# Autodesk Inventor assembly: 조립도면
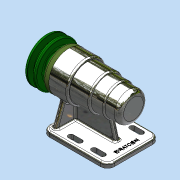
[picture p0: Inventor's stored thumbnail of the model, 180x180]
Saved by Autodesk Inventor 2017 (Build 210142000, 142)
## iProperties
Part Number: 조립도면
Material: 일반
Document SubType Name: Assembly
Designer: MRC
Author: MRC
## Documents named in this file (12)
- C:\Users\MRC\Desktop\711009V1006\답안조립품.iam
- C:\Users\MRC\Desktop\711009V1006\부품1.ipt
- C:\Users\MRC\Desktop\711009V1006\V벨트풀리.ipt
- C:\Users\MRC\Desktop\711009V1006\멈춤나사 M3.ipt
- C:\Users\MRC\Desktop\711009V1006\베어링 6004.ipt
- C:\Users\MRC\Desktop\711009V1006\베어링 51202.ipt
- C:\Users\MRC\Desktop\711009V1006\볼트 M4.ipt
- C:\Users\MRC\Desktop\711009V1006\어댑터슬리브.ipt
- C:\Users\MRC\Desktop\711009V1006\오일 실 20x35x7.ipt
- C:\Users\MRC\Desktop\711009V1006\축.ipt
- C:\Users\MRC\Desktop\711009V1006\커버.ipt
- C:\Users\MRC\Desktop\711009V1006\키 5x5.ipt
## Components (1 placed, 1 different names)
1. V벨트풀리:1
